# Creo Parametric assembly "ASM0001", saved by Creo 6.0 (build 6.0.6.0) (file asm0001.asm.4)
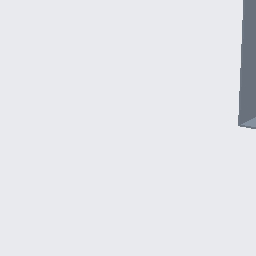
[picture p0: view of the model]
Units: Inch lbm Second (Pro/E Default); INCH, POUND, SECS

Created from: INLBS_ASM_DESIGN.ASM

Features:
  1. datum plane "ASM_RIGHT"
  2. datum plane "ASM_TOP"
  3. datum plane "ASM_FRONT"
  4. coordinate system
  5. component "PRT0001"
  6. component "LEFT"
  7. coordinate system
  8. component "BACK"
  9. component "PRT0002"
  10. component "RIGHT"

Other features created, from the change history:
  component "BACK.PRT"
  component "RIGHT.PRT"
  component "PRT0002.PRT"

Other named items: ACS4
